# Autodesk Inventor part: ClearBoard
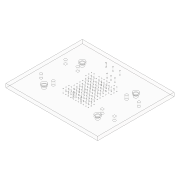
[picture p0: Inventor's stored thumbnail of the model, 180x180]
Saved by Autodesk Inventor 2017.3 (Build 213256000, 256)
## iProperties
Part Number: ClearBoard
Material: PET プラスチック
Document SubType Name: Modeling
Designer: kyushu-hep
Density: 1.541 g/cm^3
Appearance: ポリカーボネート - クリア
Author: kyushu-hep
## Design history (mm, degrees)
sketch "スケッチ1"
  geometry: L1 (60, -50)-(-60, -50); L2 (-60, -50)-(-60, 50); L3 (-60, 50)-(60, 50); L4 (60, 50)-(60, -50); L5 (60, -50)-(-60, 50); L6 (-60, -50)-(60, 50); 1 further point
  constraints: 12 end point, 2 midpoint, 2 parallel, 1 horizontal, 1 perpendicular
  dimensions: "d0" = 120 distance of L2.end L3.end; "d1" = 100 distance of L1.end L2.end
extrude "押し出し1" new body sketch "スケッチ1" distance "d2" = 5; taper "d3" = 0 deg
sketch "スケッチ3"
  geometry: C1 r 2.5 at (-35, 25); C2 r 2.5 at (35, 25); C3 r 2.5 at (-35, -25); C4 r 2.5 at (35, -25); 1 further point
  constraints: 4 centre point
  dimensions: "d11" = 5 diameter of C1; "d14" = 25 vertical distance of C1.centre point (0, 0); "d15" = 35 horizontal distance of C1.centre point (0, 0); "d18" = 5 diameter of C2; "d19" = 35 horizontal distance of point (0, 0) C2.centre; "d20" = 25 vertical distance of C2.centre point (0, 0); "d21" = 5 diameter of C3; "d22" = 25 vertical distance of point (0, 0) C3.centre; "d23" = 35 horizontal distance of point (0, 0) C3.centre; "d24" = 5 diameter of C4; "d25" = 25 vertical distance of point (0, 0) C4.centre; "d26" = 35 horizontal distance of point (0, 0) C4.centre
extrude "押し出し3" cut sketch "スケッチ3" distance "d27" = 5; taper "d28" = 0 deg
sketch "スケッチ5"
  geometry: L1 (17.5, -19.5)-(-17.5, -19.5); L2 (-17.5, -19.5)-(-17.5, 19.5); L3 (-17.5, 19.5)-(17.5, 19.5); L4 (17.5, 19.5)-(17.5, -19.5); L5 (17.5, -19.5)-(-17.5, 19.5); L6 (-17.5, -19.5)-(17.5, 19.5); C1 r 0.5 at (-16.5, 18.5); C2 r 0.5 at (-13.2, 18.5); C3 r 0.5 at (-9.9, 18.5); C4 r 0.5 at (-6.6, 18.5); C5 r 0.5 at (-3.3, 18.5); C6 r 0.5 at (0, 18.5); C7 r 0.5 at (3.3, 18.5); C8 r 0.5 at (6.6, 18.5); C9 r 0.5 at (9.9, 18.5); C10 r 0.5 at (13.2, 18.5); C11 r 0.5 at (-16.5, 14.8); C12 r 0.5 at (-13.2, 14.8); C13 r 0.5 at (-9.9, 14.8); C14 r 0.5 at (-6.6, 14.8); C15 r 0.5 at (-3.3, 14.8); C16 r 0.5 at (0, 14.8); C17 r 0.5 at (3.3, 14.8); C18 r 0.5 at (6.6, 14.8); C19 r 0.5 at (9.9, 14.8); C20 r 0.5 at (13.2, 14.8); C21 r 0.5 at (16.5, 18.5); C22 r 0.5 at (16.5, 14.8); C23 r 0.5 at (-16.5, 11.1); C24 r 0.5 at (-13.2, 11.1); C25 r 0.5 at (-9.9, 11.1); C26 r 0.5 at (-6.6, 11.1); C27 r 0.5 at (-3.3, 11.1); C28 r 0.5 at (0, 11.1); C29 r 0.5 at (3.3, 11.1); C30 r 0.5 at (6.6, 11.1); C31 r 0.5 at (9.9, 11.1); C32 r 0.5 at (13.2, 11.1); C33 r 0.5 at (16.5, 11.1); C34 r 0.5 at (-16.5, 7.4); C35 r 0.5 at (-13.2, 7.4); C36 r 0.5 at (-9.9, 7.4); C37 r 0.5 at (-6.6, 7.4); C38 r 0.5 at (-3.3, 7.4); C39 r 0.5 at (0, 7.4); C40 r 0.5 at (3.3, 7.4); C41 r 0.5 at (6.6, 7.4); C42 r 0.5 at (9.9, 7.4); C43 r 0.5 at (13.2, 7.4); C44 r 0.5 at (16.5, 7.4); C45 r 0.5 at (-16.5, 3.7); C46 r 0.5 at (-13.2, 3.7); C47 r 0.5 at (-9.9, 3.7); C48 r 0.5 at (-6.6, 3.7); C49 r 0.5 at (-3.3, 3.7); C50 r 0.5 at (0, 3.7); C51 r 0.5 at (3.3, 3.7); C52 r 0.5 at (6.6, 3.7); C53 r 0.5 at (9.9, 3.7); C54 r 0.5 at (13.2, 3.7); C55 r 0.5 at (16.5, 3.7); C56 r 0.5 at (-16.5, 0); C57 r 0.5 at (-13.2, 0); C58 r 0.5 at (-9.9, 0); C59 r 0.5 at (-6.6, 0); C60 r 0.5 at (-3.3, 0); C61 r 0.5 at (0, 0); C62 r 0.5 at (3.3, 0); C63 r 0.5 at (6.6, 0); C64 r 0.5 at (9.9, 0)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; 1 further point
  constraints: 121 centre point, 12 end point, 2 horizontal, 2 midpoint, 2 parallel, 1 perpendicular, 1 vertical, 240 other
  dimensions: "d58" = 35 distance of L2.end L3.end; "d59" = 39 distance of L3.end L1.start; "d60" = 1 diameter of C1; "d61" = 16.5 horizontal distance of point (0, 0) C1.centre; "d62" = 18.5 vertical distance of point (0, 0) C1.centre; "d65" = 3.3 distance of C1.centre C2.centre; "d68" = 3.7 distance of C1.centre C11.centre
extrude "押し出し10" cut sketch "スケッチ5" distance "d89" = 10; taper "d90" = 0 deg
sketch "スケッチ7"
  geometry: L1 (20, 20)-(-20, 20); L2 (-20, 20)-(-20, -20); L3 (-20, -20)-(20, -20); L4 (20, -20)-(20, 20); L5 (20, 20)-(-20, -20); L6 (-20, 20)-(20, -20); C1 r 1.75 at (-48, -16); C2 r 1.75 at (-48, 16); C3 r 1.75 at (-32, -16); C4 r 1.75 at (-32, 16); C5 r 1.75 at (-16, -16); C6 r 1.75 at (-16, 16); C7 r 1.75 at (0, -16); C8 r 1.75 at (0, 16); C9 r 1.75 at (16, -16); C10 r 1.75 at (16, 16); C11 r 1.75 at (32, -16); C12 r 1.75 at (32, 16); C13 r 1.75 at (48, -16); C14 r 1.75 at (48, 16); 2 further points
  constraints: 14 centre point, 12 end point, 2 horizontal, 2 midpoint, 2 parallel, 1 perpendicular, 1 vertical, 26 other
  dimensions: "d95" = 3.5 diameter of C1; "d96" = 48 horizontal distance of point (0, 0) C1.centre; "d97" = 16 vertical distance of point (0, 0) C1.centre; "d98" = 40 distance of L3.end L2.end; "d99" = 40 distance of L2.end L1.end; "d100" = 32 distance of C1.centre C2.centre; "d101" = 16 distance of C1.centre C3.centre
extrude "押し出し11" cut sketch "スケッチ7" distance "d102" = 5; taper "d103" = 0 deg
sketch "スケッチ9"
  geometry: C1 r 2.5 at (35, -25); C2 r 3.5 at (35, -25); C3 r 2.5 at (-35, -25); C4 r 3.5 at (-35, -25); C5 r 2.5 at (35, 25); C6 r 3.5 at (35, 25); C7 r 3.5 at (-35, 25); 2 further points
  constraints: 7 centre point, 3 coincident
  dimensions: "d110" = 7 diameter of C2; "d111" = 7 diameter of C4; "d112" = 7 diameter of C6; "d113" = 7 diameter of C7
extrude "押し出し13" cut sketch "スケッチ9" distance "d114" = 2; taper "d115" = 0 deg
sketch "スケッチ10"
  geometry: L1 (-90, 50)-(-90, -50); L2 (-90, -50)-(90, -50); C1 r 0.75 at (-5.05, 27.5); C2 r 0.75 at (5.05, 27.5); C3 r 0.75 at (0, 27.5); C4 r 0.75 at (0, 39); C5 r 0.75 at (-9, 39); C6 r 0.75 at (-18, 39); C7 r 0.75 at (-5.05, -16.5); C8 r 0.75 at (5.05, -16.5); 2 further points
  constraints: 8 centre point, 4 end point
  dimensions: "d117" = 1.5 diameter of C1; "d118" = 1.5 diameter of C2; "d119" = 10.1 distance of C2.centre C1.centre; "d120" = 27.5 vertical distance of point (0, 0) C2.centre; "d121" = 5.05 horizontal distance of C1.centre point (0, 0); "d122" = 10.1 distance of C2.centre C1.centre; "d123" = 1.5 diameter of C3; "d124" = 1.5 diameter of C4; "d125" = 11.5 distance of C4.centre C3.centre; "d126" = 1.5 diameter of C5; "d127" = 1.5 diameter of C6; "d128" = 9 distance of C4.centre C5.centre; "d129" = 5.05 distance of C1.centre C3.centre; "d130" = 9 distance of C5.centre C6.centre; "d131" = 1.5 diameter of C7; "d132" = 44 distance of C7.centre C1.centre; "d133" = 1.5 diameter of C8; "d134" = 44 distance of C2.centre C8.centre
extrude "押し出し14" cut sketch "スケッチ10" distance "d135" = 5; taper "d136" = 0 deg
node "ソリッド1"
